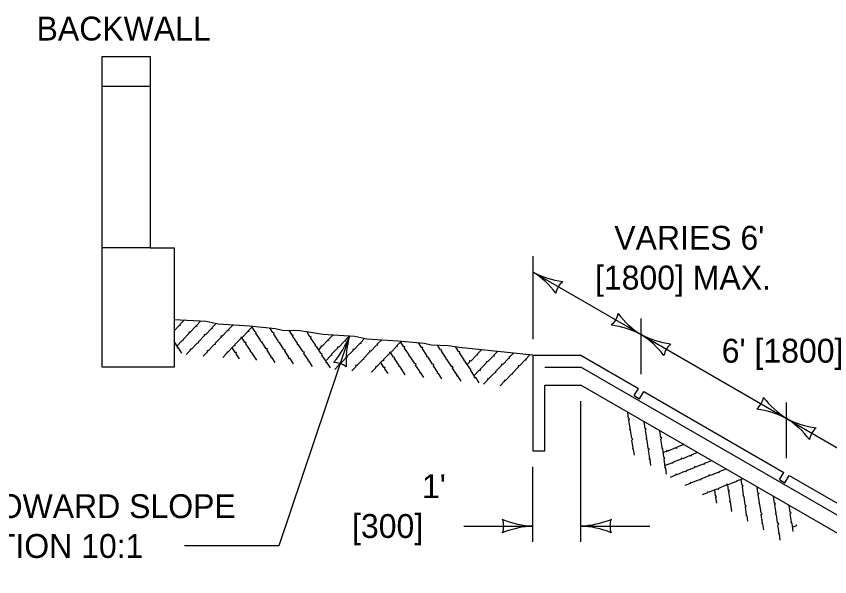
# Model space of a CAD drawing. Extents: x 49991.4 to 50021, y 49987.6 to 50011.4.
# Drawn here: x 50008.419 to 50010.46, y 49991.662 to 49993.07 of the extents above; entities that cross this region are included whole.
import ezdxf

# ---------------------------------------------------------------- set-up
doc = ezdxf.new("R2010")
doc.units = 0
for name, color, linetype in [('Level 1', 7, 'Continuous'), ('Level 2', 7, 'Continuous'), ('Level 3', 7, 'Continuous')]:
    doc.layers.add(name, color=color, linetype=linetype)

msp = doc.modelspace()

# ---------------------------------------------------------------- linework, layer by layer
at = {"layer": 'Level 1'}
for p, q in [((50008.6352, 49992.1883), (50008.6352, 49992.9687)), ((50008.6352, 49992.9687), (50008.7552, 49992.9687)), ((50008.7552, 49992.9687), (50008.7552, 49992.4884)), ((50008.6352, 49992.8938), (50008.7552, 49992.8938)), ((50008.7552, 49992.4884), (50008.6352, 49992.4884)), ((50008.7552, 49992.4884), (50008.8154, 49992.4884)), ((50008.8154, 49992.4884), (50008.8154, 49992.1883)), ((50009.7158, 49992.2185), (50009.5387, 49992.2374)), ((50009.7158, 49992.2185), (50009.7158, 49991.9781)), ((50009.7158, 49992.2185), (50009.8356, 49992.2185)), ((50009.8356, 49992.2185), (50009.9802, 49992.135)), ((50008.8154, 49992.1883), (50008.6352, 49992.1883)), ((50009.7459, 49992.1883), (50009.8357, 49992.1883)), ((50011.8116, 49991.0475), (50009.8357, 49992.1883)), ((50009.7459, 49991.9781), (50009.7459, 49992.1432)), ((50009.7459, 49992.1432), (50009.8357, 49992.1432)), ((50011.8116, 49991.0024), (50009.8357, 49992.1432)), ((50009.9698, 49992.117), (50009.9802, 49992.135)), ((50009.9832, 49992.1091), (50009.9936, 49992.1271)), ((50009.9936, 49992.1271), (50010.3451, 49991.9244)), ((50009.9698, 49992.117), (50009.9832, 49992.1091)), ((50009.7158, 49991.9781), (50009.7459, 49991.9781)), ((50010.3347, 49991.9063), (50010.3451, 49991.9244)), ((50010.3481, 49991.8985), (50010.3586, 49991.9164)), ((50010.3586, 49991.9164), (50010.71, 49991.7138)), ((50010.3347, 49991.9063), (50010.3481, 49991.8985))]:
    msp.add_line(p, q, dxfattribs=at)
for points in [[(50008.8154, 49992.3085), (50008.896, 49992.3037), (50008.926, 49992.2974), (50009.0042, 49992.292), (50009.0699, 49992.286), (50009.0877, 49992.2817), (50009.1306, 49992.2804), (50009.1633, 49992.2752), (50009.1883, 49992.2712)], [(50008.8412, 49992.307), (50008.8297, 49992.2957), (50008.8308, 49992.2931), (50008.8282, 49992.2934), (50008.8154, 49992.2799)], [(50008.8828, 49992.3046), (50008.8715, 49992.2934), (50008.8725, 49992.2909), (50008.87, 49992.2911), (50008.8557, 49992.2761), (50008.8524, 49992.2766), (50008.8526, 49992.2734), (50008.8378, 49992.2584), (50008.8375, 49992.2552), (50008.8345, 49992.2546), (50008.823, 49992.2421)], [(50008.9205, 49992.2977), (50008.9099, 49992.2871), (50008.9108, 49992.2846), (50008.9084, 49992.2849), (50008.8941, 49992.27), (50008.8908, 49992.2704), (50008.8909, 49992.2672), (50008.8762, 49992.2522), (50008.876, 49992.2492), (50008.8729, 49992.2484), (50008.8589, 49992.2336), (50008.8557, 49992.2336), (50008.8561, 49992.2305), (50008.846, 49992.2204)], [(50008.9635, 49992.2948), (50008.9521, 49992.2834), (50008.953, 49992.2808), (50008.9504, 49992.2812), (50008.9362, 49992.2662), (50008.933, 49992.2667), (50008.9331, 49992.2635), (50008.9184, 49992.2484), (50008.9181, 49992.2453), (50008.9151, 49992.2446), (50008.901, 49992.2297), (50008.898, 49992.2298), (50008.8982, 49992.2266), (50008.8882, 49992.2165)], [(50009.0129, 49992.2913), (50009.0017, 49992.2802), (50009.0026, 49992.2774), (50009.0002, 49992.2779), (50008.986, 49992.2629), (50008.9826, 49992.2632), (50008.9827, 49992.2602), (50008.968, 49992.2451), (50008.9676, 49992.242), (50008.9648, 49992.2414), (50008.9506, 49992.2264), (50008.9476, 49992.2264), (50008.9478, 49992.2234), (50008.9378, 49992.2132)], [(50009.0688, 49992.2002), (50009.0617, 49992.2118), (50009.059, 49992.2114), (50009.0598, 49992.2138), (50009.0485, 49992.231), (50009.0496, 49992.2342), (50009.0465, 49992.2348), (50009.0352, 49992.2525), (50009.0323, 49992.2535), (50009.0322, 49992.2565), (50009.0208, 49992.2736), (50009.0216, 49992.2767), (50009.0184, 49992.277), (50009.011, 49992.2891)], [(50009.1146, 49992.1966), (50009.1063, 49992.21), (50009.1036, 49992.2096), (50009.1044, 49992.212), (50009.0931, 49992.2293), (50009.0941, 49992.2323), (50009.091, 49992.233), (50009.0798, 49992.2506), (50009.077, 49992.2517), (50009.0768, 49992.2548), (50009.0655, 49992.2718), (50009.0663, 49992.2748), (50009.0631, 49992.2752), (50009.0556, 49992.2873)], [(50009.0227, 49992.2063), (50009.0098, 49992.2263), (50009.007, 49992.2273), (50009.0069, 49992.2304), (50008.9957, 49992.2475), (50008.9963, 49992.2504), (50008.9932, 49992.2508), (50008.9856, 49992.2627)], [(50009.1628, 49992.1905), (50009.1544, 49992.204), (50009.1518, 49992.2035), (50009.1524, 49992.2059), (50009.1412, 49992.2232), (50009.1423, 49992.2263), (50009.1392, 49992.227), (50009.1279, 49992.2446), (50009.1249, 49992.2456), (50009.1249, 49992.2487), (50009.1136, 49992.2658), (50009.1145, 49992.2688), (50009.1113, 49992.2692), (50009.1037, 49992.2813)], [(50009.1834, 49992.2238), (50009.1729, 49992.2404), (50009.17, 49992.2414), (50009.1699, 49992.2443), (50009.1586, 49992.2615), (50009.1593, 49992.2645), (50009.1562, 49992.2649), (50009.1483, 49992.2777)], [(50009.2141, 49992.2696), (50009.2027, 49992.2584), (50009.2037, 49992.2559), (50009.2012, 49992.2561), (50009.187, 49992.2411), (50009.1852, 49992.2414)], [(50009.1883, 49992.2712), (50009.269, 49992.2664), (50009.2989, 49992.2601), (50009.377, 49992.2548), (50009.4427, 49992.2487), (50009.4606, 49992.2444), (50009.5034, 49992.2431), (50009.5361, 49992.238), (50009.5387, 49992.2374)], [(50009.2556, 49992.2673), (50009.2443, 49992.2561), (50009.2454, 49992.2536), (50009.2428, 49992.2538), (50009.2285, 49992.2389), (50009.2252, 49992.2393), (50009.2254, 49992.2361), (50009.2106, 49992.2211), (50009.2104, 49992.2179), (50009.2075, 49992.2173), (50009.1958, 49992.2048)], [(50008.8347, 49992.2238), (50008.8265, 49992.237), (50008.8238, 49992.2366), (50008.8245, 49992.2389), (50008.8154, 49992.253)], [(50009.1852, 49992.2414), (50009.1836, 49992.2416), (50009.1838, 49992.2384), (50009.1782, 49992.2328)], [(50009.2934, 49992.2604), (50009.2828, 49992.2499), (50009.2838, 49992.2474), (50009.2813, 49992.2476), (50009.267, 49992.2328), (50009.2636, 49992.2331), (50009.2637, 49992.2299), (50009.2491, 49992.215), (50009.2488, 49992.2119), (50009.2458, 49992.2111), (50009.2317, 49992.1962), (50009.2286, 49992.1963), (50009.2289, 49992.1932), (50009.2188, 49992.1831)], [(50009.3363, 49992.2575), (50009.3249, 49992.2462), (50009.3258, 49992.2436), (50009.3234, 49992.2439), (50009.3092, 49992.2289), (50009.3059, 49992.2294), (50009.306, 49992.2262), (50009.2912, 49992.2112), (50009.291, 49992.208), (50009.2879, 49992.2073), (50009.274, 49992.1924), (50009.2708, 49992.1925), (50009.2711, 49992.1894), (50009.261, 49992.1792)], [(50009.3858, 49992.254), (50009.3745, 49992.2429), (50009.3755, 49992.2403), (50009.3731, 49992.2405), (50009.3588, 49992.2256), (50009.3555, 49992.226), (50009.3556, 49992.2228), (50009.3408, 49992.2078), (50009.3406, 49992.2047), (50009.3375, 49992.2041), (50009.3236, 49992.1892), (50009.3204, 49992.1892), (50009.3207, 49992.1861), (50009.3106, 49992.176)], [(50009.4417, 49992.1629), (50009.4346, 49992.1745), (50009.4318, 49992.1742), (50009.4327, 49992.1765), (50009.4212, 49992.1937), (50009.4224, 49992.1969), (50009.4194, 49992.1975), (50009.408, 49992.2152), (50009.4051, 49992.2162), (50009.4051, 49992.2192), (50009.3938, 49992.2363), (50009.3945, 49992.2394), (50009.3914, 49992.2397), (50009.3837, 49992.2518)], [(50009.4875, 49992.1593), (50009.4791, 49992.1727), (50009.4765, 49992.1724), (50009.4772, 49992.1748), (50009.4659, 49992.192), (50009.467, 49992.195), (50009.464, 49992.1957), (50009.4526, 49992.2134), (50009.4497, 49992.2144), (50009.4497, 49992.2175), (50009.4384, 49992.2345), (50009.4392, 49992.2376), (50009.4361, 49992.238), (50009.4284, 49992.25)], [(50009.5355, 49992.1532), (50009.5273, 49992.1667), (50009.5245, 49992.1663), (50009.5253, 49992.1688), (50009.5141, 49992.1859), (50009.5152, 49992.189), (50009.512, 49992.1897), (50009.5008, 49992.2073), (50009.4979, 49992.2084), (50009.4978, 49992.2114), (50009.4865, 49992.2285), (50009.4872, 49992.2315), (50009.4841, 49992.2319), (50009.4766, 49992.244)], [(50008.9794, 49992.2097), (50008.9715, 49992.222), (50008.9721, 49992.225), (50008.969, 49992.2253), (50008.9613, 49992.2377)], [(50009.2075, 49992.1865), (50009.1994, 49992.1997), (50009.1966, 49992.1993), (50009.1974, 49992.2016), (50009.1862, 49992.2189), (50009.1873, 49992.2221), (50009.1841, 49992.2227), (50009.1834, 49992.2238)], [(50009.3955, 49992.169), (50009.3828, 49992.189), (50009.3798, 49992.19), (50009.3798, 49992.1931), (50009.3684, 49992.2101), (50009.3692, 49992.2131), (50009.3661, 49992.2136), (50009.3587, 49992.2255)], [(50009.5563, 49992.1865), (50009.5457, 49992.2031), (50009.5428, 49992.2041), (50009.5428, 49992.207), (50009.5314, 49992.2242), (50009.5322, 49992.2272), (50009.529, 49992.2276), (50009.5211, 49992.2404)], [(50009.5869, 49992.2323), (50009.5755, 49992.2211), (50009.5766, 49992.2186), (50009.574, 49992.2188), (50009.5597, 49992.204), (50009.558, 49992.2041)], [(50009.6267, 49992.228), (50009.6172, 49992.2188), (50009.6182, 49992.2163), (50009.6157, 49992.2165), (50009.6014, 49992.2016), (50009.5982, 49992.2019), (50009.5984, 49992.1989), (50009.5836, 49992.1837), (50009.5832, 49992.1806), (50009.5803, 49992.18), (50009.5686, 49992.1677)], [(50009.6667, 49992.2237), (50009.6556, 49992.2126), (50009.6565, 49992.2101), (50009.6541, 49992.2103), (50009.6398, 49992.1955), (50009.6365, 49992.1958), (50009.6366, 49992.1926), (50009.6219, 49992.1777), (50009.6217, 49992.1747), (50009.6186, 49992.1738), (50009.6046, 49992.1589), (50009.6014, 49992.1591), (50009.6019, 49992.1559), (50009.5916, 49992.1459)], [(50009.558, 49992.2041), (50009.5564, 49992.2043), (50009.5566, 49992.2011), (50009.551, 49992.1955)], [(50009.7083, 49992.2193), (50009.6978, 49992.2089), (50009.6988, 49992.2064), (50009.6962, 49992.2066), (50009.682, 49992.1918), (50009.6786, 49992.1921), (50009.6788, 49992.1889), (50009.6641, 49992.1739), (50009.6638, 49992.1707), (50009.6608, 49992.1701), (50009.6468, 49992.1551), (50009.6437, 49992.1553), (50009.6439, 49992.1522), (50009.6339, 49992.1419)], [(50009.3523, 49992.1725), (50009.3442, 49992.1847), (50009.345, 49992.1877), (50009.3419, 49992.1881), (50009.3341, 49992.2004)], [(50009.5804, 49992.1492), (50009.5722, 49992.1624), (50009.5695, 49992.162), (50009.5702, 49992.1644), (50009.559, 49992.1816), (50009.5601, 49992.1847), (50009.5571, 49992.1854), (50009.5563, 49992.1865)], [(50009.9703, 49991.9672), (50009.9682, 49991.9827), (50009.9655, 49991.9835), (50009.9673, 49991.9853), (50009.9641, 49992.0056), (50009.9664, 49992.008), (50009.9639, 49992.0099), (50009.9608, 49992.0307), (50009.9585, 49992.0329), (50009.9597, 49992.0356), (50009.9565, 49992.0559), (50009.9584, 49992.0583), (50009.9557, 49992.06), (50009.9538, 49992.075)], [(50010.0116, 49991.9417), (50010.0096, 49991.9575), (50010.0069, 49991.9582), (50010.0086, 49991.9601), (50010.0055, 49991.9803), (50010.0078, 49991.9827), (50010.0052, 49991.9846), (50010.0023, 49992.0054), (50010, 49992.0075), (50010.0012, 49992.0103), (50009.9979, 49992.0306), (50009.9998, 49992.033), (50009.9971, 49992.0345), (50009.9949, 49992.0513)], [(50010.0442, 49991.9635), (50010.0414, 49991.9831), (50010.0391, 49991.985), (50010.0403, 49991.9879), (50010.037, 49992.0081), (50010.039, 49992.0104), (50010.0364, 49992.0122), (50010.0341, 49992.0287)], [(50010.0531, 49991.9788), (50010.0517, 49991.9796), (50010.0504, 49991.9767), (50010.0431, 49991.9739)], [(50010.0941, 49991.994), (50010.0759, 49991.9871), (50010.0758, 49991.9845), (50010.0736, 49991.9857), (50010.0545, 49991.978), (50010.0531, 49991.9789)], [(50010.0508, 49991.9196), (50010.0488, 49991.935), (50010.0462, 49991.9359), (50010.0478, 49991.9376), (50010.0447, 49991.958), (50010.0469, 49991.9604), (50010.0444, 49991.9622), (50010.0442, 49991.9635)], [(50010.1289, 49991.9739), (50010.1129, 49991.9679), (50010.1128, 49991.9652), (50010.1106, 49991.9664), (50010.0915, 49991.9586), (50010.0887, 49991.9604), (50010.0875, 49991.9575), (50010.0679, 49991.9498), (50010.0663, 49991.9472), (50010.0633, 49991.9476), (50010.0477, 49991.9413)], [(50010.1642, 49991.9535), (50010.1455, 49991.9465), (50010.1454, 49991.9438), (50010.1432, 49991.945), (50010.124, 49991.9374), (50010.1212, 49991.9391), (50010.12, 49991.9362), (50010.1004, 49991.9285), (50010.0988, 49991.9258), (50010.0959, 49991.9264), (50010.0768, 49991.9186), (50010.0741, 49991.9199), (50010.0731, 49991.917), (50010.0597, 49991.9119)], [(50010.2006, 49991.9325), (50010.1822, 49991.9258), (50010.1821, 49991.923), (50010.18, 49991.9243), (50010.1609, 49991.9166), (50010.158, 49991.9183), (50010.1568, 49991.9154), (50010.1372, 49991.9077), (50010.1357, 49991.905), (50010.1326, 49991.9056), (50010.1138, 49991.8978), (50010.111, 49991.8991), (50010.1101, 49991.8962), (50010.0966, 49991.8911)], [(50010.2425, 49991.9083), (50010.2262, 49991.9023), (50010.226, 49991.8997), (50010.2239, 49991.9009), (50010.2048, 49991.8931), (50010.2018, 49991.8948), (50010.2007, 49991.8919), (50010.181, 49991.8843), (50010.1796, 49991.8816), (50010.1766, 49991.8821), (50010.1576, 49991.8744), (50010.1548, 49991.8757), (50010.1538, 49991.8728), (50010.1404, 49991.8677)], [(50010.2546, 49991.8018), (50010.2528, 49991.8154), (50010.2501, 49991.8162), (50010.2519, 49991.818), (50010.2487, 49991.8383), (50010.251, 49991.8407), (50010.2484, 49991.8425), (50010.2454, 49991.8634), (50010.2432, 49991.8654), (50010.2444, 49991.8683), (50010.2411, 49991.8885), (50010.243, 49991.8909), (50010.2403, 49991.8925), (50010.2384, 49991.9068)], [(50010.1771, 49991.8473), (50010.1746, 49991.8617), (50010.1766, 49991.8642), (50010.1739, 49991.8659), (50010.172, 49991.8803)], [(50010.2149, 49991.8263), (50010.2115, 49991.85), (50010.2094, 49991.8519), (50010.2105, 49991.8549), (50010.2072, 49991.875), (50010.2091, 49991.8775), (50010.2064, 49991.8791), (50010.2046, 49991.8931)], [(50010.2948, 49991.7798), (50010.2928, 49991.7955), (50010.29, 49991.7962), (50010.2918, 49991.798), (50010.2886, 49991.8183), (50010.2909, 49991.8207), (50010.2884, 49991.8226), (50010.2854, 49991.8434), (50010.2831, 49991.8454), (50010.2843, 49991.8483), (50010.281, 49991.8686), (50010.283, 49991.871), (50010.2802, 49991.8725), (50010.2783, 49991.8877)], [(50010.3362, 49991.7545), (50010.3341, 49991.7701), (50010.3315, 49991.7709), (50010.3332, 49991.7727), (50010.33, 49991.7931), (50010.3323, 49991.7955), (50010.3297, 49991.7973), (50010.3268, 49991.8181), (50010.3245, 49991.8202), (50010.3257, 49991.8229), (50010.3224, 49991.8432), (50010.3244, 49991.8456), (50010.3217, 49991.8472), (50010.3193, 49991.864)], [(50010.3687, 49991.7763), (50010.3659, 49991.7957), (50010.3636, 49991.7978), (50010.3648, 49991.8006), (50010.3615, 49991.8207), (50010.3635, 49991.8231), (50010.3609, 49991.8249), (50010.3586, 49991.8413)], [(50010.3776, 49991.7914), (50010.3763, 49991.7923), (50010.3751, 49991.7895), (50010.3677, 49991.7866)]]:
    msp.add_lwpolyline(points, dxfattribs=at)
at = {"layer": 'Level 3'}
for p, q in [((50009.7159, 49992.2585), (50009.7159, 49992.4672)), ((50009.7159, 49992.4272), (50009.9869, 49992.2705)), ((50009.9869, 49992.171), (50009.9869, 49992.3105)), ((50009.2555, 49992.2672), (50009.0783, 49991.7396)), ((50009.9869, 49992.2705), (50010.3518, 49992.0598)), ((50009.8357, 49991.7497), (50009.8357, 49992.1032)), ((50010.3518, 49991.9604), (50010.3518, 49992.0998)), ((50010.3518, 49992.0598), (50010.7167, 49991.8491)), ((50009.7158, 49991.7497), (50009.7158, 49991.9381)), ((50009.5424, 49991.7897), (50009.7158, 49991.7897)), ((50009.8357, 49991.7897), (50010.0091, 49991.7897)), ((50009.0783, 49991.7396), (50008.8411, 49991.7396))]:
    msp.add_line(p, q, dxfattribs=at)
for centre, radius, start, end in [((50009.5968, 49992.2394), 0.2223, 37.4183, 57.6018), ((50009.8225, 49992.6344), 0.233, 242.7896, 262.0394), ((50009.8269, 49992.363), 0.0548, 132.1011, 167.8234), ((50009.8759, 49992.3346), 0.0548, 312.1011, 347.8234), ((50010.106, 49992.4582), 0.2223, 217.4183, 237.6018), ((50009.8804, 49992.0633), 0.233, 62.7896, 82.0394), ((50009.0479, 49992.3466), 0.2223, 318.8895, 339.073), ((50009.4798, 49992.204), 0.233, 164.2608, 183.5107), ((50009.8679, 49992.0827), 0.2223, 37.459, 57.6425), ((50010.0933, 49992.4778), 0.233, 242.8303, 262.0802), ((50010.0979, 49992.2064), 0.0548, 132.1418, 167.8642), ((50009.2147, 49992.1456), 0.0548, 53.5723, 89.2947), ((50010.2408, 49992.1239), 0.0548, 312.1418, 347.8642), ((50010.4708, 49992.2476), 0.2223, 217.459, 237.6425), ((50010.2455, 49991.8525), 0.233, 62.8303, 82.0802), ((50010.4582, 49992.2671), 0.233, 242.8303, 262.0802), ((50010.2329, 49991.872), 0.2223, 37.459, 57.6425), ((50010.4629, 49991.9957), 0.0548, 132.1418, 167.8642), ((50009.725, 49992.0118), 0.2223, 247.456, 267.6395), ((50009.5876, 49991.7897), 0.0548, 342.1388, 17.8612), ((50009.8242, 49992.0224), 0.233, 272.8273, 292.0772), ((50009.9639, 49991.7897), 0.0548, 162.1388, 197.8612), ((50009.7273, 49991.557), 0.233, 92.8273, 112.0772), ((50009.8265, 49991.5676), 0.2223, 67.456, 87.6395)]:
    msp.add_arc(centre, radius, start, end, dxfattribs=at)

# ---------------------------------------------------------------- texts
at = {"layer": 'Level 2'}
for s, p in [('BACKWALL', (50008.4703, 49993.0087)), ("VARIES 6'", (50009.9198, 49992.4834)), ('[1800] MAX.', (50009.8714, 49992.3834)), ("6' [1800]", (50010.1894, 49992.1998)), ("1'", (50009.4373, 49991.8597)), ('SLOPE TOWARD SLOPE', (50008.0339, 49991.8096)), ('[300]', (50009.2619, 49991.7597)), ('PROTECTION 10:1', (50008.0339, 49991.7096))]:
    msp.add_text(s, height=0.06, dxfattribs=at).set_placement(p)

doc.saveas('drawing.dxf')
